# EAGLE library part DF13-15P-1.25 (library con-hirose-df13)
DF13-15P 1.25mm Pitch Miniature Crimping Connector.
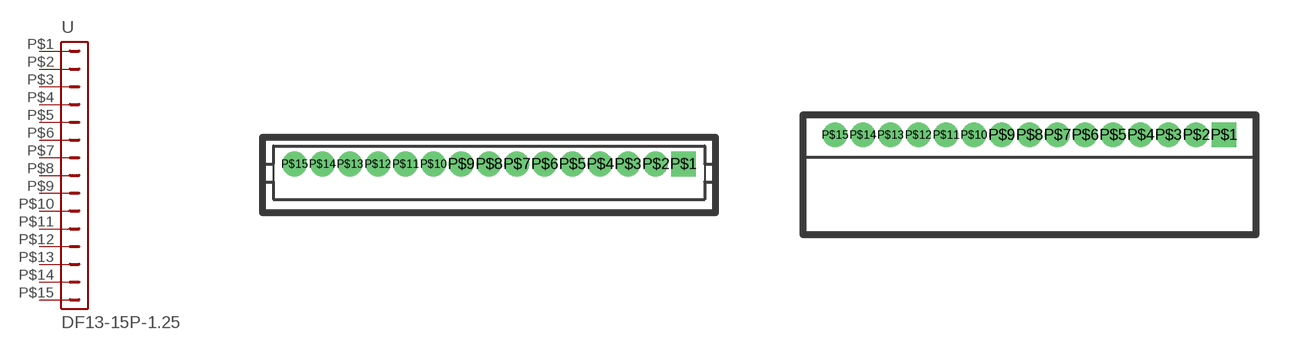
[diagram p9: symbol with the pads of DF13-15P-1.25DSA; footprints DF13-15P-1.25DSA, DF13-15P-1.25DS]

Designator prefix -

## DF13-15P-1.25DSA  [DF13-15P-1.25DSA]
P$1  1  pas
P$2  2  pas
P$3  3  pas
P$4  4  pas
P$5  5  pas
P$6  6  pas
P$7  7  pas
P$8  8  pas
P$9  9  pas
P$10  10  pas
P$11  11  pas
P$12  12  pas
P$13  13  pas
P$14  14  pas
P$15  15  pas

## DF13-15P-1.25DS  [DF13-15P-1.25DS]
Pads as for DF13-15P-1.25DSA

## DF13-15P-1.25V  [DF13C-15P-1.25V]
Pads as for DF13-15P-1.25DSA

## DF13-15P-1.25H  [DF13A-15P-1.25H]
Pads as for DF13-15P-1.25DSA

## Footprint DF13-15P-1.25DSA (pad centres in mm)
Single Row Straight Pin Header (Through hole)
drill 0.6 pad 1.016 square: P$1 8.75,0
drill 0.6 pad 1.016 round: P$2 7.5,0; P$3 6.25,0; P$4 5,0; P$5 3.75,0; P$6 2.5,0; P$7 1.25,0; P$8 0,0; P$9 -1.25,0; P$10 -2.5,0; P$11 -3.75,0; P$12 -5,0; P$13 -6.25,0; P$14 -7.5,0; P$15 -8.75,0

## Footprint DF13-15P-1.25DS (pad centres in mm)
Single Row Right Angle Pin Header (Through hole)
drill 0.6 pad 1.016 square: P$1 8.75,0
drill 0.6 pad 1.016 round: P$2 7.5,0; P$3 6.25,0; P$4 5,0; P$5 3.75,0; P$6 2.5,0; P$7 1.25,0; P$8 0,0; P$9 -1.25,0; P$10 -2.5,0; P$11 -3.75,0; P$12 -5,0; P$13 -6.25,0; P$14 -7.5,0; P$15 -8.75,0

## Footprint DF13C-15P-1.25V (pad centres in mm)
Single Row Straight Pin Header (SMT)
smd 1.6 x 2.2: M$0 11.2,-1.8; M$1 -11.2,-1.8
smd 0.7 x 1.8: P$1 -8.75,0.9; P$2 -7.5,0.9; P$3 -6.25,0.9; P$4 -5,0.9; P$5 -3.75,0.9; P$6 -2.5,0.9; P$7 -1.25,0.9; P$8 0,0.9; P$9 1.25,0.9; P$10 2.5,0.9; P$11 3.75,0.9; P$12 5,0.9; P$13 6.25,0.9; P$14 7.5,0.9; P$15 8.75,0.9

## Footprint DF13A-15P-1.25H (pad centres in mm)
Single Row Straight Pin Header (SMT)
smd 1.6 x 2.2: M$0 -11.1,2.4; M$1 11.1,2.4
smd 0.7 x 1.8: P$1 -8.75,-0.9; P$2 -7.5,-0.9; P$3 -6.25,-0.9; P$4 -5,-0.9; P$5 -3.75,-0.9; P$6 -2.5,-0.9; P$7 -1.25,-0.9; P$8 0,-0.9; P$9 1.25,-0.9; P$10 2.5,-0.9; P$11 3.75,-0.9; P$12 5,-0.9; P$13 6.25,-0.9; P$14 7.5,-0.9; P$15 8.75,-0.9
